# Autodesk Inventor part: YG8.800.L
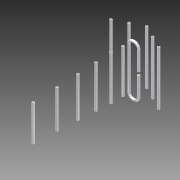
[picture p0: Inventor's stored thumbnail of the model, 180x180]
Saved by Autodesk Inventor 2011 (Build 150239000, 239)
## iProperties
Created: 2014-03
Part Number: YG8.800.L
Document SubType Name: Modeling
Designer: Evgeny
Density: 1 g/cm^3
Author: Evgeny
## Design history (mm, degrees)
sketch "Эскиз2"
  geometry: C1 r 4 at (0, 0); C2 r 3 at (0, 0); C3 r 4 at (0, -60); C4 r 3 at (0, -60); C5 r 4 at (0, 20); C6 r 3 at (0, 20); C7 r 4 at (0, 60); C8 r 3 at (0, 60); C9 r 4 at (0, 110); C10 r 3 at (0, 110); C11 r 4 at (0, 170); C12 r 3 at (0, 170); C13 r 4 at (0, 240); C14 r 3 at (0, 240); C15 r 4 at (0, 320); C16 r 3 at (0, 320); C17 r 3 at (40, -40); C18 r 4 at (40, -40); C19 r 3 at (80, -20); C20 r 4 at (80, -20); C21 r 3 at (-40, -40); C22 r 4 at (-40, -40); C23 r 3 at (-80, -20); C24 r 4 at (-80, -20); 1 further point
  constraints: 24 centre point, 13 coincident
  dimensions: "d0" = 8 diameter of C1; "d1" = 6 diameter of C2; "d2" = 8 diameter of C3; "d3" = 6 diameter of C4; "d4" = 8 diameter of C5; "d5" = 6 diameter of C6; "d6" = 8 diameter of C7; "d7" = 6 diameter of C8; "d8" = 8 diameter of C9; "d9" = 6 diameter of C10; "d10" = 8 diameter of C11; "d11" = 6 diameter of C12; "d12" = 8 diameter of C13; "d13" = 6 diameter of C14; "d14" = 8 diameter of C15; "d15" = 6 diameter of C16; "d16" = 60 distance of C3.centre point (0, 0); "d17" = 20 distance of C5.centre point (0, 0); "d18" = 60 distance of C7.centre C1.centre; "d19" = 110 distance of C9.centre point (0, 0); "d20" = 170 distance of C11.centre point (0, 0); "d21" = 240 distance of C13.centre C1.centre; "d22" = 320 distance of C15.centre point (0, 0); "d56" = 8 diameter of C18; "d57" = 6 diameter of C17; "d58" = 8 diameter of C20; "d59" = 6 diameter of C19; "d60" = 40 horizontal distance of C18.centre C4.centre; "d61" = 40 horizontal distance of C20.centre C17.centre; "d62" = 20 vertical distance of C17.centre C3.centre; "d63" = 40 vertical distance of C20.centre C3.centre; "d64" = 8 diameter of C22; "d65" = 6 diameter of C21; "d66" = 8 diameter of C24; "d67" = 6 diameter of C23; "d68" = 40 horizontal distance of C21.centre C3.centre; "d69" = 40 horizontal distance of C24.centre C22.centre; "d70" = 20 vertical distance of C21.centre C3.centre; "d71" = 40 vertical distance of C23.centre C3.centre
extrude "Выдавливание1" new body sketch "Эскиз2" stored distance "d23" = 180; taper "d24" = 0 deg
extrude "Выдавливание2" join sketch "Эскиз2" stored distance "d25" = 146; taper "d26" = 0 deg
extrude "Выдавливание3" join sketch "Эскиз2" stored distance "d27" = 147; taper "d28" = 0 deg
extrude "Выдавливание4" join sketch "Эскиз2" stored distance "d29" = 141; taper "d30" = 0 deg
extrude "Выдавливание6" join sketch "Эскиз2" stored distance "d33" = 134; taper "d34" = 0 deg
extrude "Выдавливание7" join sketch "Эскиз2" stored distance "d35" = 127; taper "d36" = 0 deg
extrude "Выдавливание8" join sketch "Эскиз2" stored distance "d37" = 120; taper "d38" = 0 deg
sketch "Эскиз3"
  geometry: L1 (15, 84)-(18, 84); L2 (18, -84)-(15, -84); L3 (0, -69)-(0, 69); L4 (33, 69)-(33, 5); L5 (33, -5)-(33, -69); A1 r 15 centre (15, 69) between (15, 84) and (0, 69); A2 r 15 centre (18, 69) between (33, 69) and (18, 84); A3 r 15 centre (18, -69) between (18, -84) and (33, -69); A4 r 15 centre (15, -69) between (0, -69) and (15, -84); 1 further point
  constraints: 10 end point, 10 tangent, 8 point on circle, 4 centre point, 3 equal radius, 3 parallel, 2 perpendicular, 1 horizontal
  dimensions: "d50" = 168 distance between parallel lines of L1 L2; "d51" = 84 distance from line of point (0, 0) L2; "d52" = 15 radius of A1; "d53" = 5 vertical distance of L4.end point (0, 0); "d54" = 10 distance of L5.start L4.end; "d74" = 33 distance between parallel lines of L4 L3
feature "Сдвиг1" sketch "Эскиз3" dims "d55" = 0
extrude "Выдавливание9" join sketch "Эскиз2" stored distance "d72" = 180; taper "d73" = 0 deg
node "Твердое тело1"
